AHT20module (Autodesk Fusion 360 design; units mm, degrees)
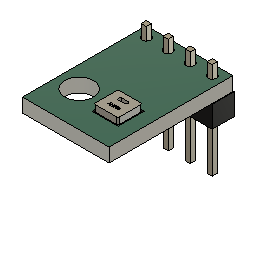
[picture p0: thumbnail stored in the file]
sketch "スケッチ1" plane through (0, 0, 0) normal (0, 1, 0) x axis (1, 0, 0)
  line L1 (3, 0) -> (0, 0)
  line L2 (3, -3) -> (3, 0)
  line L3 (0, -3) -> (3, -3)
  line L4 (0, 0) -> (0, -3)
  line L5 (0.5, 0) -> (0, 0)
  line L6 (0.5, -3) -> (0.5, 0)
  line L7 (0, -3) -> (0.5, -3)
  line L8 (0, 0) -> (0, -3)
  line L9 (2.5, 0) -> (3, 0)
  line L10 (2.5, -3) -> (2.5, 0)
  line L11 (3, -3) -> (2.5, -3)
  line L12 (3, 0) -> (3, -3)
  line L13 (3, 0) -> (0, 0)
  line L14 (3, -1.5) -> (3, 0)
  line L15 (0, -1.5) -> (3, -1.5)
  line L16 (0, 0) -> (0, -1.5)
  line L17 (3, -1.5) -> (0, -1.5)
  line L18 (3, -0.5) -> (3, -1.5)
  line L19 (0, -0.5) -> (3, -0.5)
  line L20 (0, -1.5) -> (0, -0.5)
  line L21 (3, -1.5) -> (0, -1.5)
  line L22 (3, -2.5) -> (3, -1.5)
  line L23 (0, -2.5) -> (3, -2.5)
  line L24 (0, -1.5) -> (0, -2.5)
  line L25 (0.225, -0.5) -> (0.5, -0.5)
  line L26 (0.225, -0.3) -> (0.225, -0.5)
  line L27 (0.5, -0.3) -> (0.225, -0.3)
  line L28 (0.5, -0.5) -> (0.5, -0.3)
  line L29 (0.775, -0.3) -> (0.225, -0.3)
  line L30 (0.775, -0.7) -> (0.775, -0.3)
  line L31 (0.225, -0.7) -> (0.775, -0.7)
  line L32 (0.225, -0.3) -> (0.225, -0.7)
  line L33 (0.775, -1.7) -> (0.775, -1.3)
  line L34 (0.225, -1.7) -> (0.775, -1.7)
  line L35 (0.775, -1.3) -> (0.225, -1.3)
  line L36 (0.225, -1.3) -> (0.225, -1.5)
  line L37 (0.225, -1.3) -> (0.225, -1.7)
  line L38 (2.775, -0.3) -> (2.225, -0.3)
  line L39 (2.225, -0.3) -> (2.225, -0.7)
  line L40 (2.225, -0.7) -> (2.775, -0.7)
  line L41 (2.775, -0.7) -> (2.775, -0.3)
  line L42 (2.775, -1.3) -> (2.225, -1.3)
  line L43 (2.225, -1.3) -> (2.225, -1.5)
  line L44 (2.225, -1.3) -> (2.225, -1.7)
  line L45 (2.225, -1.7) -> (2.775, -1.7)
  line L46 (2.775, -1.7) -> (2.775, -1.3)
  line L47 (0.775, -2.3) -> (0.225, -2.3)
  line L48 (0.225, -2.7) -> (0.775, -2.7)
  line L49 (0.225, -2.3) -> (0.225, -2.7)
  line L50 (0.775, -2.7) -> (0.775, -2.3)
  line L51 (2.225, -2.3) -> (2.225, -2.7)
  line L52 (2.775, -2.7) -> (2.775, -2.3)
  line L53 (2.775, -2.3) -> (2.225, -2.3)
  line L54 (2.225, -2.7) -> (2.775, -2.7)
  line L55 (0.1, -3) -> (0, -3)
  line L56 (0.1, -2.9) -> (0.1, -3)
  line L57 (0, -2.9) -> (0.1, -2.9)
  line L58 (0, -3) -> (0, -2.9)
  line L59 (2.9, -2.9) -> (0.1, -2.9)
  line L60 (2.9, -0.1) -> (2.9, -2.9)
  line L61 (0.1, -0.1) -> (2.9, -0.1)
  line L62 (0.1, -2.9) -> (0.1, -0.1)
  line L63 (-5.44, 0) -> (0, 0)
  line L64 (-5.44, 8.69) -> (-5.44, 0)
  line L65 (0, 8.69) -> (-5.44, 8.69)
  line L66 (0, 0) -> (0, 8.69)
  line L67 (-4.25, 8.69) -> (-5.44, 8.69)
  line L68 (-4.25, 7.5) -> (-4.25, 8.69)
  line L69 (-5.44, 7.5) -> (-4.25, 7.5)
  line L70 (-5.44, 8.69) -> (-5.44, 7.5)
  line L71 (-1.71, 7.5) -> (-4.25, 7.5)
  line L72 (-1.71, 8.69) -> (-1.71, 7.5)
  line L73 (-4.25, 8.69) -> (-1.71, 8.69)
  line L74 (-4.25, 7.5) -> (-4.25, 8.69)
  line L75 (0.83, 7.5) -> (-1.71, 7.5)
  line L76 (0.83, 8.69) -> (0.83, 7.5)
  line L77 (-1.71, 8.69) -> (0.83, 8.69)
  line L78 (-1.71, 7.5) -> (-1.71, 8.69)
  line L79 (3.37, 7.5) -> (0.83, 7.5)
  line L80 (3.37, 8.69) -> (3.37, 7.5)
  line L81 (0.83, 8.69) -> (3.37, 8.69)
  line L82 (0.83, 7.5) -> (0.83, 8.69)
  line L83 (4.56, 7.5) -> (3.37, 7.5)
  line L84 (4.56, 8.69) -> (4.56, 7.5)
  line L85 (3.37, 8.69) -> (4.56, 8.69)
  line L86 (3.37, 7.5) -> (3.37, 8.69)
  line L87 (4.56, 8.69) -> (-5.44, 8.69)
  line L88 (4.56, -5.6) -> (4.56, 8.69)
  line L89 (-5.44, -5.6) -> (4.56, -5.6)
  line L90 (-5.44, 8.69) -> (-5.44, -5.6)
  line L91 (-3, 7.5) -> (-4.25, 7.5)
  line L92 (-3, -1.5) -> (-3, 7.5)
  line L93 (-4.25, -1.5) -> (-3, -1.5)
  line L94 (-4.25, 7.5) -> (-4.25, -1.5)
  line L95 (-5.52, 7.5) -> (-4.25, 7.5)
  line L96 (-5.52, 8.77) -> (-5.52, 7.5)
  line L97 (-4.25, 8.77) -> (-5.52, 8.77)
  line L98 (-4.25, 7.5) -> (-4.25, 8.77)
  line L99 (4.64, 7.5) -> (3.37, 7.5)
  line L100 (4.64, 6.23) -> (4.64, 7.5)
  line L101 (3.37, 6.23) -> (4.64, 6.23)
  line L102 (3.37, 7.5) -> (3.37, 6.23)
  line L103 (4.64, 8.77) -> (-5.52, 8.77)
  line L104 (4.64, 6.23) -> (4.64, 8.77)
  line L105 (-5.52, 6.23) -> (4.64, 6.23)
  line L106 (-5.52, 8.77) -> (-5.52, 6.23)
  line L107 (-4.55, 7.5) -> (-4.25, 7.5)
  line L108 (-4.55, 7.8) -> (-4.55, 7.5)
  line L109 (-4.25, 7.8) -> (-4.55, 7.8)
  line L110 (-4.25, 7.5) -> (-4.25, 7.8)
  line L111 (-3.95, 7.8) -> (-4.55, 7.8)
  line L112 (-3.95, 7.2) -> (-3.95, 7.8)
  line L113 (-4.55, 7.2) -> (-3.95, 7.2)
  line L114 (-4.55, 7.8) -> (-4.55, 7.2)
  line L115 (-1.41, 7.8) -> (-2.01, 7.8)
  line L116 (-1.41, 7.2) -> (-1.41, 7.8)
  line L117 (-2.01, 7.2) -> (-1.41, 7.2)
  line L118 (-2.01, 7.8) -> (-2.01, 7.2)
  line L119 (1.13, 7.8) -> (0.53, 7.8)
  line L120 (1.13, 7.2) -> (1.13, 7.8)
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  point P1 (0, 0)
  point P2 (0, 0)
  point P6 (0, 0)
  point P15 (3, -1.5)
  point P13 (0, 0)
  point P23 (0.5, -0.5)
  point P80 (-3, -1.5)
  point P82 (-3, -1.5)
  point P62 (-4.25, 7.5)
  point P83 (-4.25, 7.5)
  point P64 (-1.71, 7.5)
  point P84 (-1.71, 7.5)
  point P67 (0.83, 7.5)
  point P85 (0.83, 7.5)
  point P70 (3.37, 7.5)
  point P86 (3.37, 7.5)
  point P87 (-4.25, 7.5)
  point P91 (3.37, 7.5)
  point P97 (-4.25, 7.5)
  point P3 (3, 0)
  point P5 (0, -3)
  point P7 (0.5, 0)
  point P10 (2.5, 0)
  point P16 (0, -1.5)
  point P19 (0, -0.5)
  point P22 (0, -2.5)
  point P24 (0.225, -0.5)
  point P25 (0.225, -0.3)
  point P27 (0.775, -0.3)
  point P29 (0.225, -0.7)
  point P31 (0.225, -1.3)
  point P33 (0.775, -1.3)
  point P32 (0.225, -1.7)
  point P35 (2.225, -0.3)
  point P42 (2.775, -0.3)
  point P41 (2.225, -0.7)
  point P37 (2.225, -1.3)
  point P39 (2.775, -1.3)
  point P38 (2.225, -1.7)
  point P44 (0.225, -2.3)
  point P46 (0.775, -2.3)
  point P45 (0.225, -2.7)
  point P49 (2.775, -2.3)
  point P50 (2.225, -2.3)
  point P51 (2.225, -2.7)
  point P9 (0, -3)
  point P52 (0.1, -3)
  point P54 (0, -2.9)
  point P53 (0.1, -2.9)
  point P55 (2.9, -2.9)
  point P57 (0.1, -0.1)
  point P58 (-5.44, 0)
  point P60 (0, 8.69)
  point P59 (-5.44, 8.69)
  point P61 (-4.25, 8.69)
  point P63 (-5.44, 7.5)
  point P72 (0.83, 8.69)
  point P73 (4.56, 7.5)
  point P75 (3.37, 8.69)
  point P76 (4.56, 8.69)
  point P78 (-5.44, -5.6)
  point P79 (-3, 7.5)
  point P81 (-4.25, -1.5)
  point P88 (-5.52, 7.5)
  point P90 (-4.25, 8.77)
  point P92 (4.64, 7.5)
  point P94 (3.37, 6.23)
  point P98 (-4.55, 7.5)
  point P100 (-4.25, 7.8)
  point P99 (-4.55, 7.8)
  point P101 (-3.95, 7.8)
  point P103 (-4.55, 7.2)
  point P104 (-1.41, 7.8)
  point P106 (-2.01, 7.8)
  point P105 (-2.01, 7.2)
  point P108 (1.13, 7.8)
  point P110 (0.53, 7.8)
  point P109 (0.53, 7.2)
  point P113 (3.07, 7.8)
  point P115 (3.67, 7.8)
  point P112 (3.07, 7.2)
  horizontal L1
  vertical L2
  horizontal L3
  vertical L4
  coincident P1 P2
  horizontal L5
  vertical L6
  horizontal L7
  vertical L8
  coincident P1 P6
  horizontal L9
  vertical L10
  horizontal L11
  vertical L12
  horizontal L13
  vertical L14
  horizontal L15
  vertical L16
  midpoint L12 P15
  coincident P1 P13
  horizontal L17
  vertical L18
  horizontal L19
  vertical L20
  horizontal L21
  vertical L22
  horizontal L23
  vertical L24
  horizontal L25
  vertical L26
  horizontal L27
  vertical L28
  coincident L6 P23
  coincident L19 P23
  horizontal L29
  vertical L30
  horizontal L31
  vertical L32
  vertical L36
  horizontal L35
  vertical L33
  horizontal L34
  vertical L37
  horizontal L38
  vertical L41
  horizontal L40
  vertical L39
  vertical L43
  horizontal L42
  vertical L46
  horizontal L45
  vertical L44
  horizontal L47
  vertical L50
  horizontal L48
  vertical L49
  horizontal L53
  vertical L52
  horizontal L54
  vertical L51
  horizontal L55
  vertical L56
  horizontal L57
  vertical L58
  horizontal L59
  vertical L60
  horizontal L61
  vertical L62
  horizontal L63
  vertical L64
  horizontal L65
  vertical L66
  horizontal L67
  vertical L68
  horizontal L69
  vertical L70
  horizontal L71
  vertical L72
  horizontal L73
  vertical L74
  horizontal L75
  vertical L76
  horizontal L77
  vertical L78
  horizontal L79
  vertical L80
  horizontal L81
  vertical L82
  horizontal L83
  vertical L84
  horizontal L85
  vertical L86
  horizontal L87
  vertical L88
  horizontal L89
  vertical L90
  horizontal L91
  vertical L92
  horizontal L93
  vertical L94
  coincident P80 P82
  coincident P62 P83
  coincident P64 P84
  coincident P67 P85
  coincident P70 P86
  horizontal L95
  vertical L96
  horizontal L97
  vertical L98
  coincident P83 P87
  horizontal L99
  vertical L100
  horizontal L101
  vertical L102
  coincident P86 P91
  horizontal L103
  vertical L104
  horizontal L105
  vertical L106
  horizontal L107
  vertical L108
  horizontal L109
  vertical L110
  coincident P83 P97
  horizontal L111
  vertical L112
  horizontal L113
  vertical L114
  horizontal L115
  vertical L116
  horizontal L117
  vertical L118
  horizontal L119
  vertical L120
  dimension "d1" distance P2 P3 = 3
  dimension "d2" distance P2 P5 = 3
  dimension "d3" distance P6 P7 = 0.5
  dimension "d4" distance P3 P10 = 0.5
  dimension "d5" distance P13 P16 = 1.5
  dimension "d6" distance P16 P19 = 1
  dimension "d7" distance P16 P22 = 1
  dimension "d8" distance P23 P24 = 0.275 (= "( 0.55 / 2 ) * 1 mm")
  dimension "d9" distance P25 P27 = 0.55
  dimension "d10" distance P25 P29 = 0.4
  dimension "d11" distance P31 P33 = 0.55
  dimension "d12" distance P31 P32 = 0.4
  dimension "d13" distance P35 P42 = 0.55
  dimension "d14" distance P35 P41 = 0.4
  dimension "d15" distance P37 P39 = 0.55
  dimension "d16" distance P37 P38 = 0.4
  dimension "d17" distance P44 P46 = 0.55
  dimension "d18" distance P44 P45 = 0.4
  dimension "d19" distance P49 P50 = 0.55
  dimension "d20" distance P50 P51 = 0.4
  dimension "d23" distance P9 P52 = 0.1
  dimension "d24" distance P9 P54 = 0.1
  dimension "d25" distance P53 P55 = 2.8
  dimension "d26" distance P53 P57 = 2.8
  dimension "d54" distance P13 P58 = 5.44 (= "4.25 mm + 1.19 mm")
  dimension "d55" distance P13 P60 = 8.69 (= "1.19 mm + 7.5 mm")
  dimension "d56" distance P59 P61 = 1.19
  dimension "d57" distance P59 P63 = 1.19
  dimension "d58" distance P62 P64 = 2.54
  dimension "d59" distance P64 P67 = 2.54
  dimension "d60" distance P67 P70 = 2.54
  dimension "d61" distance P67 P72 = 1.19
  dimension "d62" distance P70 P73 = 1.19
  dimension "d63" distance P70 P75 = 1.19
  dimension "d64" distance P59 P76 = 10 (= "8.81 mm + 1.19 mm")
  dimension "d65" distance P59 P78 = 14.29 (= "13.1 mm + 1.19 mm")
  dimension "d66" distance P62 P79 = 1.25
  dimension "d67" distance P62 P81 = 9
  dimension "d68" diameter = 3.31 (= "( 1.655 * 2 ) * 1 mm")
  dimension "d69" diameter = 1
  dimension "d70" diameter = 1
  dimension "d71" diameter = 1
  dimension "d72" diameter = 1
  dimension "d73" distance P87 P88 = 1.27
  dimension "d74" distance P87 P90 = 1.27
  dimension "d75" distance P91 P92 = 1.27
  dimension "d76" distance P91 P94 = 1.27
  dimension "d77" distance P97 P98 = 0.3
  dimension "d78" distance P97 P100 = 0.3
  dimension "d79" distance P99 P101 = 0.6
  dimension "d80" distance P99 P103 = 0.6
  dimension "d81" distance P104 P106 = 0.6
  dimension "d82" distance P105 P106 = 0.6
  dimension "d83" distance P108 P110 = 0.6
  dimension "d84" distance P109 P110 = 0.6
  dimension "d85" distance P113 P115 = 0.6
  dimension "d86" distance P112 P113 = 0.6
extrude "押し出し2" new body sketch "スケッチ1" profile of L6 L10 L15 L17 L19 L21 L23 L25 L26 L27 L28 L29 L30 L31 L32 L33 L34 L35 L36 L37 L38 L39 L40 L41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 along normal blind 0.75 bodies "AHT20-cover"
extrude "押し出し3" new body sketch "スケッチ1" profile of L1 L2 L3 L4 L5 L6 L7 L8 L9 L10 L11 L12 L13 L14 L15 L16 L17 L18 L19 L20 L21 L22 L23 L24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 against normal blind 0.25 bodies "AHT20-base"
extrude "押し出し4" new body sketch "スケッチ1" profile of L6 L10 L15 L17 L19 L21 L23 L25 L26 L27 L28 L29 L30 L31 L32 L33 L34 L35 L36 L37 L38 L39 L40 L41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 against normal blind 0.25 bodies "AHT20-pad4", "AHT20-pad1", "AHT20-pad3", "AHT20-pad5", "AHT20-pad6", "AHT20-pad2"
sketch "スケッチ2" plane through (0, 0.75, 0) normal (0, 1, 0) x axis (-1, 0, 0)
  line L1 (-0.1, 2.9) -> (-0.1, 0.1)
  line L2 (-2.9, 2.9) -> (-0.1, 2.9)
  line L3 (-2.9, 0.1) -> (-2.9, 2.9)
  line L4 (-0.1, 0.1) -> (-2.9, 0.1)
  line L5 (-0.95, 0.1) -> (-0.1, 0.1)
  line L6 (-0.95, 0.7) -> (-0.95, 0.1)
  line L7 (-0.1, 0.7) -> (-0.95, 0.7)
  line L8 (-0.1, 0.1) -> (-0.1, 0.7)
  line L9 (-2.05, 0.7) -> (-0.95, 0.7)
  line L10 (-2.05, 1.1) -> (-2.05, 0.7)
  line L11 (-0.95, 1.1) -> (-2.05, 1.1)
  line L12 (-0.95, 0.7) -> (-0.95, 1.1)
  line L13 (-1.15, 1.1) -> (-0.95, 1.1)
  line L14 (-1.15, 0.9) -> (-1.15, 1.1)
  line L15 (-0.95, 0.9) -> (-1.15, 0.9)
  line L16 (-0.95, 1.1) -> (-0.95, 0.9)
  line L17 (-1.85, 0.7) -> (-2.05, 0.7)
  line L18 (-1.85, 0.9) -> (-1.85, 0.7)
  line L19 (-2.05, 0.9) -> (-1.85, 0.9)
  line L20 (-2.05, 0.7) -> (-2.05, 0.9)
  curve K1
  curve K2
  curve K3
  curve K4
  arc A1 centre (-1.15, 0.9) radius 0.2 clockwise from (-1.15, 1.1) to (-1.15, 0.7)
  arc A2 centre (-1.85, 0.9) radius 0.2 clockwise from (-1.85, 0.7) to (-1.85, 1.1)
  point P2 (-0.1, 0.1)
  point P6 (-0.1, 0.1)
  point P17 (-1.15, 0.7)
  point P14 (-1.15, 0.9)
  point P16 (-1.15, 0.9)
  point P23 (-1.85, 1.1)
  point P20 (-1.85, 0.9)
  point P22 (-1.85, 0.9)
  point P7 (-0.95, 0.1)
  point P9 (-0.1, 0.7)
  point P8 (-0.95, 0.7)
  point P10 (-2.05, 0.7)
  point P12 (-0.95, 1.1)
  point P13 (-1.15, 1.1)
  point P15 (-0.95, 0.9)
  point P19 (-1.85, 0.7)
  point P21 (-2.05, 0.9)
  horizontal L5
  vertical L6
  horizontal L7
  vertical L8
  coincident P2 P6
  horizontal L9
  vertical L10
  horizontal L11
  vertical L12
  horizontal L13
  vertical L14
  horizontal L15
  vertical L16
  coincident L9 P17
  coincident P14 P16
  horizontal L17
  vertical L18
  horizontal L19
  vertical L20
  coincident L11 P23
  coincident P20 P22
  dimension "d33" distance P6 P7 = 0.85
  dimension "d34" distance P6 P9 = 0.6
  dimension "d35" distance P8 P10 = 1.1
  dimension "d36" distance P8 P12 = 0.4
  dimension "d37" distance P12 P13 = 0.2
  dimension "d38" distance P12 P15 = 0.2
  dimension "d39" distance P10 P19 = 0.2
  dimension "d40" distance P10 P21 = 0.2
  dimension "d51" Text1-Height = 0.3
extrude "押し出し5" cut sketch "スケッチ2" profile of L9 L11 L12 L14 L15 A1 L18 L19 A2 against normal blind 0.75
fillet "フィレット1" radius 0.2
fillet "フィレット2" radius 0.2
fillet "フィレット3" radius 0.2
fillet "フィレット4" radius 0.2
extrude "押し出し6" cut sketch "スケッチ2" against normal blind 0.1
extrude "押し出し7" new body sketch "スケッチ1" against normal blind 4.1 (magnitude of "-2.5 mm - 1.6 mm") bodies "PinHeaderBase"
extrude "押し出し8" cut sketch "スケッチ1" against normal blind 1.6
extrude "押し出し9" new body sketch "スケッチ1" against normal blind 1.6 bodies "PCB"
extrude "押し出し10" new body sketch "スケッチ1" against normal blind 9.77 (magnitude of "-5.67 mm - 2.5 mm - 1.6 mm") bodies "pin2", "pin3", "pin1", "pin4"
extrude "押し出し11" add of existing geometry blind 1.4 (= "3 mm - 1.6 mm")
extrude "押し出し12" cut sketch "スケッチ1" against normal blind 3.1
named bodies: "AHT20-cover", "AHT20-base", "AHT20-pad4", "AHT20-pad1", "AHT20-pad3", "AHT20-pad5", "AHT20-pad6", "AHT20-pad2", "PinHeaderBase", "PCB", "pin2", "pin3", "pin1", "pin4"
